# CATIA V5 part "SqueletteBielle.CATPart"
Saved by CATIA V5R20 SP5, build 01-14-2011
Part number: SqueletteBielle
Publications: "Droite.1", "Droite.2"
Bounding box of the stored display mesh (mm): x 0 to 0, y 220 to 280, z -20 to 100
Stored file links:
  F:\IAO_bmadec\bmadecf\SqueletteBielle.CATPart
  F:\IAO_bmadec\bmadecf\squelette.CATProduct
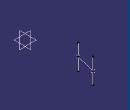
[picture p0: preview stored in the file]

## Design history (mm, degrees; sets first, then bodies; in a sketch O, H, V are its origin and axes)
Set1
  Plane1: linked copy from another document
  Point1: linked copy from another document
  Point2: linked copy from another document
Set2
  Line1: type Normal, RefPoint Point1, RefSkin Plane1, Start -50, End 50
  Line2: type Normal, RefPoint Point2, RefSkin Plane1, Start -50, End 50
  Line3: type PtPt, FirstPoint Point1, SecondPoint Point2
Body1 (main body)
